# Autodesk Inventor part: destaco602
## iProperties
Title: destaco602
Author: GJOHNST2
Shininess: 20.0
Length Units: 11272
Angle Units: 11286
Time Units: 11279
Mass Units: 11290
Length Display Precision: 3
Angle Display Precision: 2
Compacted: True
PropertySet Name: _Private Model Information
Created: 2001-11
Part Number: side
Document SubType Name: Modeling
Designer: GJOHNST2
Control State: 0
Master: False
Checked Out: False
PropertySet Name: Design Tracking Control
Density: 0.0
Volumn: 0.0
Area: 0.0
PropertySet Name: Model Information
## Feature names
1. Extrusion1
